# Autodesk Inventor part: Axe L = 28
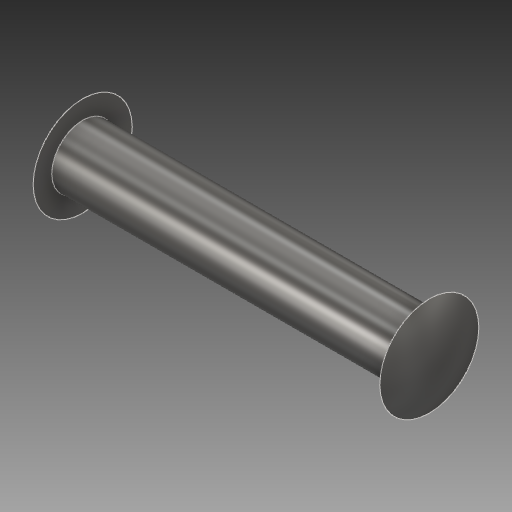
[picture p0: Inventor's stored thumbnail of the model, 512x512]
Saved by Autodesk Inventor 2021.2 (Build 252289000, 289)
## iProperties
Created: 2018-06
Part Number: Axe L = 28
Material: Acier inoxydable
Document SubType Name: Modeling
Designer: Fabian Perrée
Density: 8 g/cm^3
Appearance: Semi-poli
Author: Fabian Perrée
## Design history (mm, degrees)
sketch "Esquisse1"
  geometry: L1 (-14, 0)-(14, 0); L2 (14, 2.5)-(-14, 2.5); L3 (14, 2.5)-(14, 4); L4 (14, 0)-(15.072, 0); L5 (0, 2.5)-(0, 0); L6 (-14, 2.5)-(-14, 4); L7 (-15.072, 0)-(-14, 0); A1 r 8 centre (7.072, 0) between (15.072, 0) and (14, 4); A2 r 8 centre (-7.072, 0) between (-14, 4) and (-15.072, 0); 1 further point
  constraints: 14 end point, 4 horizontal, 4 point on circle, 3 symmetric about line, 2 centre point, 2 midpoint, 2 point on line, 1 coincident, 1 perpendicular, 1 vertical, 1 other
  dimensions: "d0" = 28 distance of L1.start L1.end; "d1" = 5 diameter of L2 L1; "d2" = 8 diameter of L3.end L1; "d3" = 16 diameter of A1
revolve "Révolution1" sketch "Esquisse1" stored, may be unused: angle "d4" = 90 deg
node "Solide1"
